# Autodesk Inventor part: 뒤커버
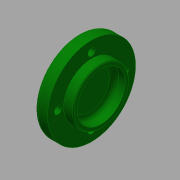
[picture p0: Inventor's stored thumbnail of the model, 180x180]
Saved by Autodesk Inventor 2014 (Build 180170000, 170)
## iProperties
Created: 2015-12
Part Number: 뒤커버
Material: 일반
Document SubType Name: Modeling
Designer: mduedu
Density: 1 g/cm^3
Appearance: 진녹색
Author: mduedu
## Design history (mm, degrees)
sketch "스케치1"
  geometry: L1 (0, 0)-(14, 0); L2 (14, 0)-(14, 17.5); L3 (14, 17.5)-(8, 17.5); L4 (8, 17.5)-(8, 27.5); L5 (8, 27.5)-(0, 27.5); L6 (0, 27.5)-(0, 0)
  constraints: 12 end point, 4 parallel, 1 horizontal, 1 perpendicular
  dimensions: "d0" = 14 distance between parallel lines of L2 L6; "d2" = 8 distance of L4.end L5.end; "d3" = 55 diameter of L5 L1; "d4" = 35 diameter of L3 L1
revolve "회전1" sketch "스케치1" stored, may be unused: angle "d5" = 90 deg
hole "구멍1" diameter "d8" = 30; stored, may be unused: countersink angle "d12" = 90 deg, drill point angle "d14" = 0 deg; dims "d9" = 6, "d10" = 4, "d11" = 2, "d13" = 7, "d39" = 10, "d40" = 10
fillet "모깎기3" dims "d38" = 2
fillet "모깎기4" dims "d41" = 3
chamfer "모따기2" distance "d42" = 0.5; stored, may be unused: second distance "d43" = 2, angle "d44" = 45 deg
sketch "스케치2" dims "d45" = 42
  geometry: 6 further points
  constraints: 2 vertical alignment, 1 coincident, 7 other
  dimensions: "d48" = 360 deg dimension on point (0, 0) point (0, 21) (derived)
sketch "스케치3"
  geometry: 4 further points
hole "구멍4" sketch "스케치3" at (-21, 0), (0, -21), (21, 0), (0, 21) diameter "d50" = 4.5; stored, may be unused: countersink angle "d54" = 90 deg, drill point angle "d56" = 0 deg; dims "d51" = 6, "d52" = 8, "d53" = 4.6, "d55" = 8
node "솔리드1"
